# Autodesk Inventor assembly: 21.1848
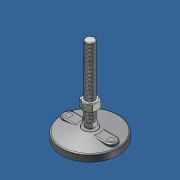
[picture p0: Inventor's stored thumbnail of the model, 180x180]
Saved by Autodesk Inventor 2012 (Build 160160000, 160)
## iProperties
Created: 2007-03
Part Number: 21.1848
Document SubType Name: Assembly
Designer: Andy Moles
Description: LEVELING FOOT M16 WITH ATTACHMENT BORES
Author: Andy Moles
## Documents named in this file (5)
- C:\Andys Backup Data\ANDY'S INVENTOR\INVENTOR LIBRARIES\PARTS LIBRARY\FEET WHEELS FLOOR FASTENING SUPPORTS\21.1848 LEVELING FOOT M16 WITH BORES.iam
- C:\Andys Backup Data\ANDY'S INVENTOR\INVENTOR LIBRARIES\PARTS LIBRARY\FEET WHEELS FLOOR FASTENING SUPPORTS\SUBCOMPONENTS\LEVELING FEET SUBCOMPONENTS\PAD 100mm GRAY PLASTIC WITH BORES.IPT
- C:\Andys Backup Data\ANDY'S INVENTOR\INVENTOR LIBRARIES\PARTS LIBRARY\FEET WHEELS FLOOR FASTENING SUPPORTS\SUBCOMPONENTS\LEVELING FEET SUBCOMPONENTS\ANTI-SKID PAD 100mm WITH BORES.ipt
- C:\Andys Backup Data\ANDY'S INVENTOR\INVENTOR LIBRARIES\PARTS LIBRARY\FASTENING ELEMENTS\NUTS\21.1529 M16 HEX NUT.ipt
- C:\Andys Backup Data\ANDY'S INVENTOR\INVENTOR LIBRARIES\PARTS LIBRARY\FEET WHEELS FLOOR FASTENING SUPPORTS\SUBCOMPONENTS\LEVELING FEET SUBCOMPONENTS\THREADED STUD 16mm SHORTER.ipt
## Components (4 placed, 4 different names)
1. ANTI-SKID PAD 100mm WITH BORES:1 — Insert:1, Mate:4
2. PAD 100mm GRAY PLASTIC WITH BORES:1 — Insert:1, Tangent:1, Mate:1, Mate:4
3. THREADED STUD 16mm SHORTER:1 — Tangent:1, Mate:1, Mate:2
4. 21.1529 M16 HEX NUT:1 — Mate:2
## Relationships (5: Mate 3, Insert 1, Tangent 1)
- Insert:1: ANTI-SKID PAD 100mm WITH BORES:1 ↔ PAD 100mm GRAY PLASTIC WITH BORES:1
- Tangent:1: PAD 100mm GRAY PLASTIC WITH BORES:1 ↔ THREADED STUD 16mm SHORTER:1
- Mate:1: PAD 100mm GRAY PLASTIC WITH BORES:1 ↔ THREADED STUD 16mm SHORTER:1
- Mate:2: THREADED STUD 16mm SHORTER:1 ↔ 21.1529 M16 HEX NUT:1
- Mate:4: ANTI-SKID PAD 100mm WITH BORES:1 ↔ PAD 100mm GRAY PLASTIC WITH BORES:1
